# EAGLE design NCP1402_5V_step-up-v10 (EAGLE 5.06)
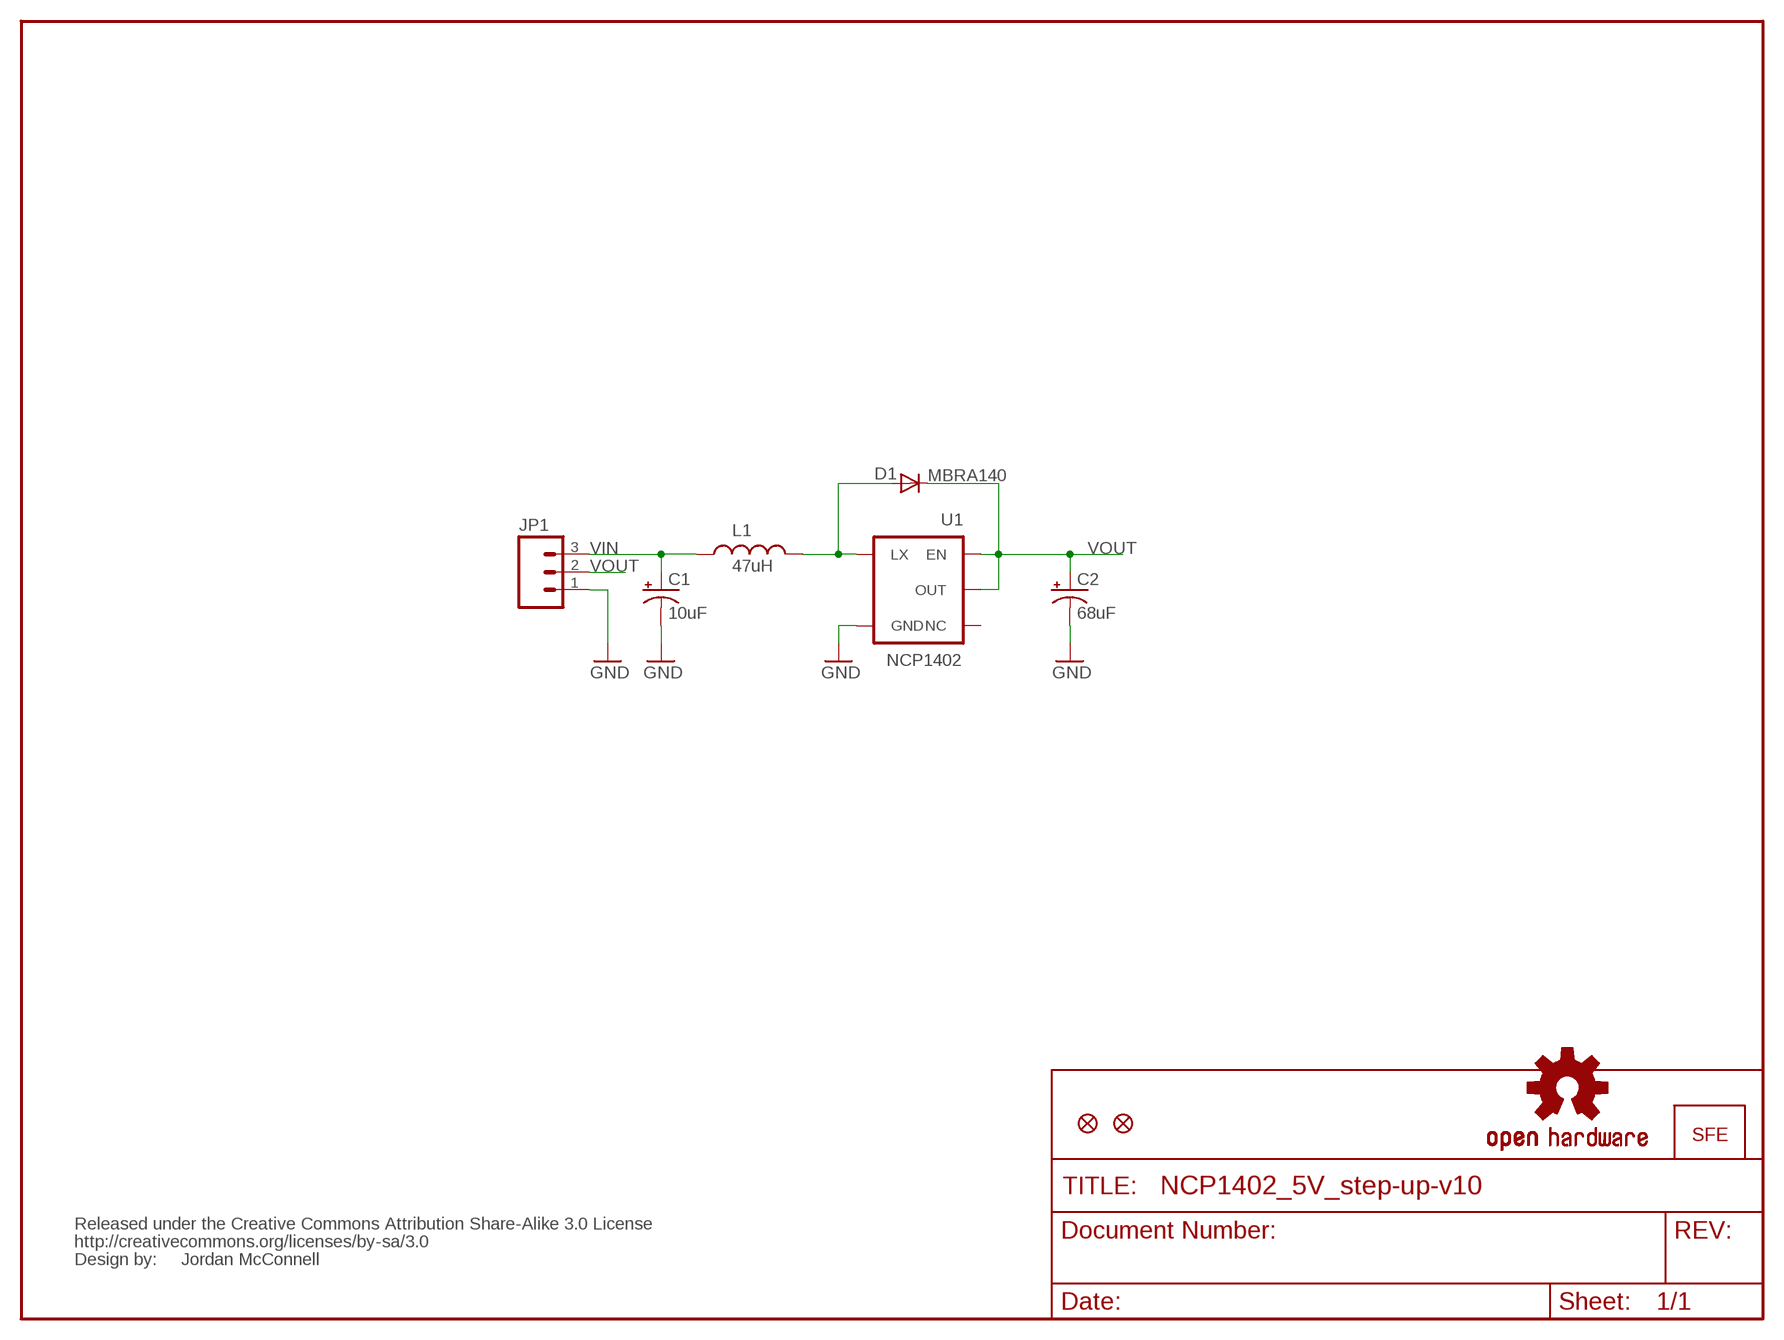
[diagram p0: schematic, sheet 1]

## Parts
C1  10uF  CAP_POL1206  [EIA3216]
C2  68uF  CAP_POL3528  [EIA3528]
D1  MBRA140  DIODESMA  [SMA-DIODE]
JP1  M03PTH  [1X03]
JP2  LOGO-SFESK  [SFE-LOGO-FLAME]
JP3  FIDUCIALUFIDUCIAL  [MICRO-FIDUCIAL]
JP4  FIDUCIALUFIDUCIAL  [MICRO-FIDUCIAL]
L1  47uH  INDUCTORCR54  [CR54]
U1  NCP1402  V_REG_NCP1400SOT23-5  [SOT23-5]
U$1  OSHW-LOGOS  [OSHW-LOGO-S]
U$2  CREATIVE_COMMONS  [CREATIVE_COMMONS]

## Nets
GND: C1.C(-) C2.C(-) JP1.1 U1.4(GND)
N$3: D1.A L1.P$2 U1.5(LX)
VIN: C1.A(+) JP1.3 L1.P$1
VOUT: C2.A(+) D1.C JP1.2 U1.1(EN) U1.2(OUT)
Unconnected: U1.3(NC)

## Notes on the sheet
- Jordan McConnell

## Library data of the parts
C1 C2 = SparkFun:CAP_POL: Capacitor Polarized
D1 = SparkFun:DIODE: Diode
JP1 = SparkFun:M03: Header 3 Standard 3-pin 0.1" header. Use with straight break away headers (SKU : PRT-00116), right angle break away headers (PRT-00553), swiss pins (PRT-00743), machine pins (PRT-00117), and female headers (PRT-00115). Molex polarized connector foot print use with SKU : PRT-08232 with associated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
JP2 = SparkFun:LOGO-SFE: Spark Fun Electronics PCB Logo
JP3 JP4 = SparkFun:FIDUCIAL: Fiducial Alignment Points
L1 = SparkFun:INDUCTOR: Inductors
U1 = SparkFun:V_REG_NCP1400: Switching step-up voltage regulator NCP1400 switiching regulator takes single cell AA and outputs 100mA at 3.3V or 5V with minimal number of external components.
U$1 = SparkFun:OSHW-LOGO: Open Source Hardware Logo This logo indicates the piece of hardware it is found on incorporates a OSHW license and/or adheres to the definition of open source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
U$2 = SparkFun:CREATIVE_COMMONS

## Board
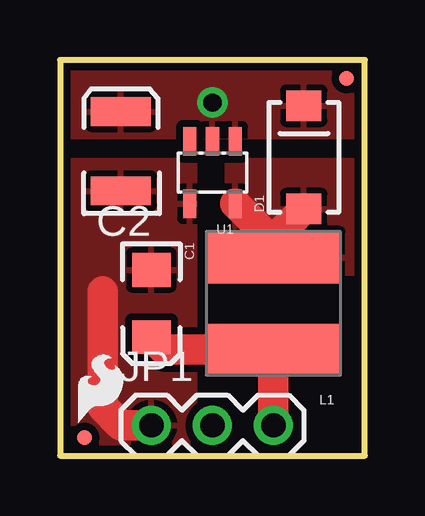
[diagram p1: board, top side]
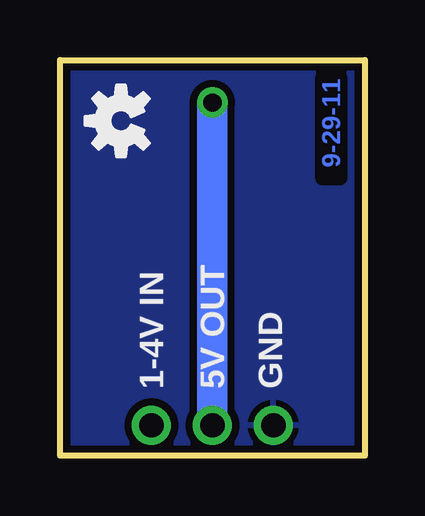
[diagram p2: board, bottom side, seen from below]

Size 12.7 x 16.51 mm. Coordinates in mm from the lower left corner, seen from the top.
Outline: 0,0 12.7,0 12.7,16.51 0,16.51 0,0
Copper layers (1*16): Top 0.035mm / dielectric 1.5mm / Bottom 0.035mm
Design rules "SparkFun *": minimum track width 8mil, minimum drill 20mil, track to track 8mil, track to pad 8mil, pad to pad 8mil, via to via 8mil, smd to smd 8mil, copper to edge 8mil, drill to drill 8mil, minimum pad ring 12mil, minimum via ring 10mil, stop-mask expansion 4mil, vias tented up to drill 20mil, thermal gap 10mil

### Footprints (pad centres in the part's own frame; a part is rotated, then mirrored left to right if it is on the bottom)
EIA3216 = smd 1.4 x 1.6: A 1.4,0; C -1.4,0
EIA3528 = smd 1.2 x 2.5: A 1.65,0; C -1.65,0
SMA-DIODE = smd 1.27 x 1.47: A -2.15,0; C 2.15,0
1X03 = drill 1.016 round: 1 0,0; 2 2.54,0; 3 5.08,0
MICRO-FIDUCIAL = smd 0.635 x 0.635: 1 0,0
CR54 = smd 5.5 x 2.15: P$1 0,1.92; P$2 0,-1.92
SOT23-5 = smd 0.55 x 1.2: 1 -0.95,-1.3; 2 0,-1.3; 3 0.95,-1.3; 4 0.95,1.3; 5 -0.95,1.3

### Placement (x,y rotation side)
C1  3.81,6.35 270 top
C2  2.54,12.7 90 top
D1  10.16,12.45 90 top
JP1  3.81,1.27 0 top
JP2  0.76,1.4 0 top
JP3  11.94,15.75 0 top
JP4  1.02,0.76 0 top
L1  8.89,6.35 180 top
U1  6.35,11.81 180 top
U$1  10.16,13.97 90 bottom
U$2  not placed on the board

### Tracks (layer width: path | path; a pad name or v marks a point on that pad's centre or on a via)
GND
  Top 1.27: JP1.1 2.54,1.27 1.78,2.03 1.78,6.86
  pour Top (isolate 0.305): 0,12.32 5.59,12.32 5.59,0.25 0,0.25
  pour Bottom (isolate 0.305): 0,0 0,16.51 12.7,16.51 12.7,0
N$3
  Top 1.27: D1.A 8.89,9.03 L1.P$2 8.89,8.92 U1.5
  pour Top (isolate 0.305): 6.99,12.32 12.7,12.32 12.7,7.62 6.99,7.62
VIN
  Top 1.27: L1.P$1 JP1.3 | 8.88,4.45 4.32,4.45 C1.A
  Top 1.524: 8.88,4.45 L1.P$1
VOUT  (via drill 0.76)
  Bottom 1.27: JP1.2 v6.35,14.73
  pour Top (isolate 0.305): 12.7,16.51 0,16.51 0,13.34 12.7,13.34

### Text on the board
Bottom: 9-29-11
bPlace: GND | 5V OUT | 1-4V IN
tValues: Jordan McConnell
